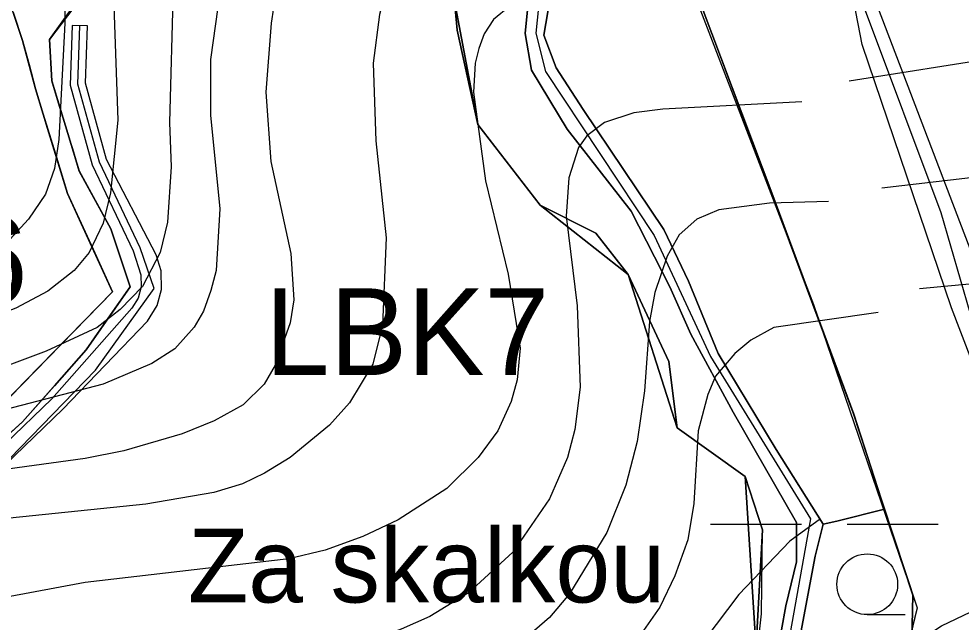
# Model space of a CAD drawing. Extents: x -1900516 to -575031, y -3809306 to -1157387.
# Drawn here: x -578987.9 to -578770.8, y -1159222.4 to -1159083.3 of the extents above; entities that cross this region are included whole.
import ezdxf

# ---------------------------------------------------------------- set-up
doc = ezdxf.new("R2010")
doc.units = 0
for name, color, linetype in [('01_MÍSTNÍ_NÁZVY', 7, 'Continuous'), ('01_OBVOD PÚ', 7, 'Continuous'), ('01_PARCELY_NÁVRH_PC', 7, 'Continuous'), ('01_PARCELY_NÁVRH_ŽP', 7, 'Continuous'), ('01_VRSTEVNICE', 7, 'Continuous'), ('02_KULTURY STAV', 7, 'Continuous'), ('03_PC_NÁVRH', 7, 'Continuous'), ('04_ZPF_OP_ORGAN', 7, 'Continuous'), ('05_VHO_V_TOK', 7, 'Continuous'), ('06_ÚSES_BK', 7, 'Continuous'), ('06_ÚSES_IP', 7, 'Continuous')]:
    doc.layers.add(name, color=color, linetype=linetype)

msp = doc.modelspace()

# ---------------------------------------------------------------- linework, layer by layer
at = {"layer": '01_OBVOD PÚ'}
msp.add_lwpolyline([(-578993.07, -1159173.58), (-578966.32, -1159146.21), (-578972.28, -1159133.19), (-578976.68, -1159123.58), (-578981.27, -1159108.56), (-578983.27, -1159102.02), (-578984.05, -1159099.45), (-578985.53, -1159093.95), (-578987.05, -1159088.32), (-578989.37, -1159081.4)], dxfattribs=at)
at = {"layer": '01_PARCELY_NÁVRH_PC'}
msp.add_lwpolyline([(-578999.92, -1159194.65), (-578977.74, -1159173.26), (-578958.23, -1159153.03), (-578956.02, -1159149.36), (-578955.02, -1159145.68), (-578955.13, -1159141.44), (-578956.29, -1159137.75), (-578967.7, -1159115.75), (-578972.58, -1159098.16), (-578972.11, -1159084.97), (-578975.61, -1159084.85), (-578976.1, -1159098.58), (-578971, -1159116.99), (-578961.55, -1159136.77), (-578959.79, -1159142.3), (-578959.73, -1159145.08), (-578960.42, -1159147.67), (-578961.87, -1159149.99), (-578980.3, -1159170.87), (-579002.02, -1159191.81)], dxfattribs=at)
at = {"layer": '01_PARCELY_NÁVRH_ŽP'}
for points in [[(-578972.07, -1159075.77), (-578980.86, -1159088.08), (-578980.33, -1159097.58), (-578977.16, -1159107.98), (-578976.36, -1159110.59), (-578975.56, -1159113.2), (-578973.97, -1159118.42), (-578970.34, -1159125.1), (-578966.74, -1159131.73), (-578962.23, -1159145.08), (-578967.3, -1159152.33), (-578972.38, -1159159.58), (-578979.72, -1159167.88), (-578987.06, -1159176.18), (-578995.06, -1159183.4)], [(-578993.07, -1159173.58), (-578979.7, -1159159.9), (-578966.32, -1159146.21), (-578969.3, -1159139.7), (-578972.28, -1159133.19), (-578976.68, -1159123.58), (-578982.27, -1159105.29), (-578984.05, -1159099.45), (-578987.05, -1159088.32), (-578989.24, -1159081.79)]]:
    msp.add_lwpolyline(points, dxfattribs=at)
at = {"layer": '01_VRSTEVNICE'}
for points in [[(-578909.33, -1159015.78), (-578918.97, -1159035.64), (-578926.52, -1159063.04), (-578929.74, -1159084.3), (-578931, -1159100.24), (-578929.88, -1159116.18), (-578925.26, -1159137.43), (-578924.57, -1159148.06), (-578925.4, -1159153.37), (-578928.84, -1159163.17), (-578931.36, -1159167.55), (-578936.22, -1159172.25), (-578942.88, -1159175.99), (-578950.29, -1159178.96), (-578963.71, -1159182.87), (-578972.66, -1159184.69), (-579002.31, -1159188.74), (-579014.89, -1159191.54), (-579073.61, -1159208.46), (-579108.57, -1159216.57), (-579135.42, -1159223.56), (-579145.66, -1159226.49), (-579157.79, -1159231.25), (-579178.62, -1159241.74)], [(-578934.07, -1159023.76), (-578933.79, -1159035.64), (-578934.63, -1159047.39), (-578938.13, -1159065), (-578942.04, -1159080.66), (-578943.72, -1159092.69), (-578943.72, -1159105.55), (-578941.62, -1159127.08), (-578942.46, -1159141.34), (-578943.66, -1159145.93), (-578945.4, -1159150.71), (-578947.5, -1159154.35), (-578951.97, -1159159.38), (-578957.28, -1159162.74), (-578968.47, -1159167.49), (-578993.08, -1159173.92)], [(-578950.01, -1159034.94), (-578952.39, -1159075.91), (-578953.23, -1159107.23), (-578952.81, -1159117.44), (-578953.65, -1159130.16), (-578955.33, -1159137.15), (-578959.38, -1159144.98), (-578964.54, -1159150.35), (-578969.87, -1159154.49), (-578981.61, -1159159.94), (-579047.05, -1159184.41), (-579064.67, -1159190.28), (-579086.2, -1159195.03), (-579137.09, -1159201.47), (-579142.98, -1159202.5), (-579150.8, -1159204.82), (-579163.66, -1159209.86), (-579181.14, -1159219.08), (-579204.21, -1159235.16), (-579204.77, -1159235.71)], [(-578965.67, -1159046.41), (-578966.23, -1159053.54), (-578966.23, -1159073.67), (-578965.11, -1159106.67), (-578966.79, -1159123.45), (-578968.47, -1159130.44), (-578971.69, -1159137.15), (-578975.18, -1159141.34), (-578981.19, -1159146.1), (-578988.6, -1159150.01), (-579008.18, -1159157.56), (-579059.91, -1159179.52), (-579073.61, -1159183.71), (-579087.32, -1159186.09), (-579132.62, -1159189.3), (-579142.69, -1159191.26), (-579148.19, -1159192.4), (-579156.11, -1159195.18), (-579177.78, -1159204.96), (-579197.22, -1159215.59), (-579203.16, -1159219.39)], [(-578873.53, -1159049.06), (-578881.78, -1159049.06), (-578884.99, -1159050.05), (-578888.49, -1159051.86), (-578894.78, -1159057.17), (-578900.38, -1159066.12), (-578904.85, -1159082.34), (-578906.25, -1159093.53), (-578905.69, -1159111.42), (-578903.31, -1159133.79), (-578904.15, -1159153.93), (-578906.39, -1159162.88), (-578911.7, -1159171.82), (-578916.32, -1159177), (-578925.4, -1159184.41), (-578931.28, -1159188.04), (-578936.41, -1159190.51), (-578943.02, -1159192.52), (-578958.68, -1159195.18), (-578990, -1159198.39)], [(-578976.02, -1159053.4), (-578977.28, -1159071.43), (-578977.28, -1159084.3), (-578978.68, -1159111.14), (-578979.65, -1159117.85), (-578981.75, -1159123.73), (-578985.67, -1159129.46), (-578990, -1159134.21), (-578996.85, -1159139.67), (-579027.75, -1159156.58), (-579055.72, -1159168.89), (-579065.64, -1159171.88), (-579079.21, -1159174.62), (-579090.95, -1159176.3), (-579132.06, -1159178.54), (-579145.76, -1159180.35), (-579153.59, -1159182.03), (-579167.15, -1159186.09), (-579177.92, -1159190.42), (-579189.67, -1159196.71), (-579196.78, -1159200.62), (-579201.55, -1159203.88)], [(-578874.79, -1159080.38), (-578878.56, -1159083.46), (-578880.73, -1159086.74), (-578881.92, -1159090.17), (-578882.76, -1159093.53), (-578883.18, -1159100.24), (-578880.38, -1159120.65), (-578875.21, -1159142.18), (-578872.41, -1159159.24), (-578873.11, -1159166.51), (-578874.51, -1159171.55), (-578877.58, -1159178.26), (-578882.06, -1159184.41), (-578889.33, -1159191.54), (-578900.52, -1159198.81), (-578908.65, -1159202.66), (-578917.3, -1159205.8), (-578925.68, -1159207.76), (-578972.66, -1159213.21), (-578991.12, -1159216.71)], [(-578761.67, -1159092.13), (-578796.63, -1159097.72)], [(-578807.54, -1159102.47), (-578839.55, -1159104.15), (-578846.27, -1159104.99), (-578852.98, -1159107.23), (-578857.03, -1159110.3), (-578858.99, -1159112.96), (-578861.23, -1159119.95), (-578861.82, -1159128.77), (-578859.27, -1159149.45), (-578858.57, -1159168.19), (-578859.83, -1159177.98), (-578861.51, -1159184.41), (-578865.7, -1159193.92), (-578874.09, -1159206.22), (-578884.3, -1159215.59), (-578893.24, -1159221.04), (-578899.82, -1159223.97), (-578911.42, -1159228.31), (-578924.01, -1159230.83), (-578933.79, -1159231.95), (-578953.93, -1159232.37), (-578968.47, -1159233.63), (-578985.25, -1159236.28), (-579000.91, -1159241.46)], [(-578768.67, -1159119.95), (-578789.08, -1159122.33)], [(-578801.38, -1159125.41), (-578814.95, -1159125.82), (-578826.69, -1159127.36), (-578831.72, -1159129.46), (-578835.78, -1159133.09), (-578838.58, -1159137.99), (-578841.37, -1159146.38), (-578842.63, -1159153.09), (-578843.75, -1159169.03), (-578845.43, -1159180.77), (-578848.08, -1159190.84), (-578852.42, -1159201.75), (-578861.09, -1159215.87), (-578865.7, -1159221.32), (-578874.23, -1159228.73), (-578885.7, -1159235.72), (-578893.53, -1159239.22), (-578902.66, -1159241.96), (-578915.06, -1159244.95), (-578963.71, -1159249.99), (-578978.82, -1159252.64), (-579009.02, -1159260.61)], [(-578638.35, -1159161.34), (-578649.4, -1159156.3), (-578666.18, -1159150.43), (-578682.95, -1159146.38), (-578708.12, -1159141.9), (-578718.54, -1159140.72), (-578729.66, -1159140.78), (-578780.41, -1159145.54)], [(-578789.92, -1159150.99), (-578813.97, -1159154.49), (-578819.28, -1159157.42), (-578823, -1159160.45), (-578827.39, -1159165.67), (-578829.21, -1159169.87), (-578831.44, -1159178.26), (-578832.42, -1159195.04), (-578833.82, -1159203.43), (-578836.76, -1159211.67), (-578840.25, -1159218.95), (-578846.69, -1159228.17), (-578859.83, -1159242.02), (-578869.34, -1159249.57), (-578880.38, -1159256.14), (-578888.21, -1159259.91), (-578900.8, -1159264.39), (-578913.38, -1159267.32), (-578931.99, -1159269.74), (-578950.76, -1159270.53), (-578967.77, -1159269.7), (-578983.57, -1159271.8), (-579008.46, -1159279.21)], [(-578803.2, -1159198.53), (-578810.33, -1159203.7), (-578822.08, -1159216.01), (-578842.91, -1159243.69), (-578854.52, -1159257.4), (-578861.02, -1159263.74), (-578870.18, -1159271.8), (-578883.46, -1159279.63), (-578890.17, -1159282.42), (-578901.35, -1159285.92), (-578912.54, -1159288.44), (-578937.15, -1159290.25), (-578959.52, -1159293.19), (-578986.37, -1159298.22), (-579017.69, -1159308.99)]]:
    msp.add_lwpolyline(points, dxfattribs=at)
at = {"layer": '02_KULTURY STAV'}
for points in [[(-578878.72, -1159008.57), (-578865.04, -1158997.83), (-578847.93, -1159038.28), (-578830.76, -1159080.15), (-578814.18, -1159124.01), (-578795.58, -1159174.4), (-578788.46, -1159196.37), (-578799.5, -1159199.1), (-578802.6, -1159199.77), (-578813.43, -1159182.6), (-578826.84, -1159160.45), (-578833.68, -1159143.82), (-578839.33, -1159131.86), (-578857.93, -1159104.24), (-578864.15, -1159094.62), (-578866.97, -1159087.11), (-578864.76, -1159074.04), (-578863.71, -1159058.92), (-578866.16, -1159041.64), (-578873.49, -1159017.14)], [(-578750.96, -1159216.07), (-578745.95, -1159212.49), (-578765.93, -1159143.8), (-578789.9, -1159081.01), (-578779.34, -1159073.2), (-578780.39, -1159072.12), (-578785.57, -1159075.82), (-578792.92, -1159081.42), (-578775.53, -1159127.99), (-578762.13, -1159174.04)], [(-578810.26, -1159237.93), (-578806.81, -1159219.87), (-578804.43, -1159207.13), (-578802.6, -1159199.77), (-578799.5, -1159199.1), (-578788.46, -1159196.37), (-578781.95, -1159216.17), (-578782.18, -1159226.7), (-578802.44, -1159228.63), (-578801.45, -1159255.16), (-578799.47, -1159271.13)]]:
    msp.add_lwpolyline(points, close=True, dxfattribs=at)
for points in [[(-578574.68, -1159052.93), (-578611.17, -1159089.26), (-578632.65, -1159109.54), (-578649.76, -1159125.08), (-578643.29, -1159133.51), (-578654.77, -1159144.71), (-578648.75, -1159152.41), (-578653.27, -1159153.89), (-578654.54, -1159154.47), (-578716.11, -1159192.14), (-578726.86, -1159198.82), (-578745.95, -1159212.49), (-578765.93, -1159143.8), (-578789.9, -1159081.01)], [(-578891.5, -1159058.08), (-578882.17, -1159107.67), (-578867.83, -1159126.24), (-578855, -1159132.74), (-578847.52, -1159142.23), (-578838.19, -1159162.33), (-578836.27, -1159177.56), (-578820.56, -1159188.8), (-578817.85, -1159232.29)], [(-578817.85, -1159232.29), (-578820.56, -1159188.8), (-578836.27, -1159177.56), (-578838.19, -1159162.33), (-578847.52, -1159142.23), (-578855, -1159132.74), (-578867.83, -1159126.24), (-578882.17, -1159107.67), (-578891.5, -1159058.08)], [(-578814.21, -1159235.22), (-578811.26, -1159218.58), (-578808.77, -1159208.5), (-578808.76, -1159199.41), (-578823.33, -1159173.97), (-578833.13, -1159156.03), (-578837.96, -1159145.12), (-578846.88, -1159127.63), (-578861.6, -1159108.78), (-578869.82, -1159095.18), (-578871.28, -1159086.72), (-578869.03, -1159064.22)], [(-578869.03, -1159064.22), (-578871.28, -1159086.72), (-578869.82, -1159095.18), (-578861.6, -1159108.78), (-578846.88, -1159127.63), (-578837.96, -1159145.12), (-578833.13, -1159156.03), (-578823.33, -1159173.97), (-578808.76, -1159199.41), (-578808.77, -1159208.5), (-578811.26, -1159218.58), (-578814.21, -1159235.22)], [(-578864.76, -1159074.04), (-578866.97, -1159087.11), (-578864.15, -1159094.62), (-578857.93, -1159104.24), (-578839.33, -1159131.86), (-578833.68, -1159143.82), (-578826.84, -1159160.45), (-578813.43, -1159182.6), (-578802.6, -1159199.77), (-578804.43, -1159207.13), (-578806.81, -1159219.87), (-578810.26, -1159237.93)], [(-578739.9, -1159419.59), (-578781.83, -1159408.23), (-578819.78, -1159397.99), (-578834.95, -1159391.81), (-578816.57, -1159357.48), (-578798.39, -1159319.53), (-578795.16, -1159304.69), (-578796.15, -1159292.03), (-578799.47, -1159271.13), (-578801.45, -1159255.16), (-578802.44, -1159228.63), (-578782.18, -1159226.7), (-578781.95, -1159216.17), (-578788.46, -1159196.37), (-578795.58, -1159174.4), (-578814.18, -1159124.01), (-578830.76, -1159080.15)], [(-578739.9, -1159419.59), (-578781.83, -1159408.23), (-578819.78, -1159397.99), (-578834.95, -1159391.81), (-578816.57, -1159357.48), (-578798.39, -1159319.53), (-578795.16, -1159304.69), (-578796.15, -1159292.03), (-578799.47, -1159271.13), (-578801.45, -1159255.16), (-578802.44, -1159228.63), (-578782.18, -1159226.7), (-578781.95, -1159216.17), (-578788.46, -1159196.37), (-578795.58, -1159174.4), (-578814.18, -1159124.01), (-578830.76, -1159080.15)], [(-578993.07, -1159173.58), (-578966.32, -1159146.21), (-578972.28, -1159133.19), (-578976.68, -1159123.58), (-578981.27, -1159108.56), (-578983.27, -1159102.02), (-578984.05, -1159099.45), (-578985.53, -1159093.95), (-578987.05, -1159088.32), (-578989.24, -1159081.79)], [(-578792.92, -1159081.42), (-578775.53, -1159127.99), (-578762.13, -1159174.04)], [(-578792.92, -1159081.42), (-578775.53, -1159127.99), (-578762.13, -1159174.04)], [(-578828.6, -1159199.77), (-578807.6, -1159199.77)], [(-578797.1, -1159199.77), (-578776.1, -1159199.77)], [(-578792.47, -1159220.64), (-578783.72, -1159220.64)]]:
    msp.add_lwpolyline(points, dxfattribs=at)
msp.add_circle((-578792.47, -1159213.64), 7, dxfattribs=at)
at = {"layer": '03_PC_NÁVRH'}
msp.add_lwpolyline([(-579215.95, -1159443), (-579197.17, -1159431.39), (-579158.1, -1159403.48), (-579144.16, -1159382.97), (-579128.89, -1159358.02), (-579121.35, -1159334.32), (-579125.5, -1159322.44), (-579117.12, -1159313.8), (-579116.13, -1159309.29), (-579151.57, -1159271.29), (-579158.84, -1159254.47), (-579157.24, -1159244.6), (-579150.76, -1159236.03), (-579103.57, -1159230.86), (-579083.6, -1159225.15), (-579037.45, -1159215.89), (-578997.46, -1159192.24), (-578970.28, -1159164.33), (-578956.73, -1159145.48), (-578959.93, -1159136.11), (-578969.35, -1159116.37), (-578974.34, -1159098.37), (-578973.86, -1159084.91)], dxfattribs=at)
at = {"layer": '04_ZPF_OP_ORGAN'}
for points in [[(-578762.04, -1159183.36), (-578765.87, -1159168.76), (-578773.07, -1159149.94), (-578793.65, -1159089.25), (-578795.58, -1159079.34), (-578795.27, -1159075.99), (-578791.37, -1159071.9), (-578791.69, -1159068.99), (-578805.61, -1158990.49), (-578808.68, -1158974.26), (-578809.14, -1158971.01), (-578808.11, -1158968.03), (-578813.28, -1158970.34), (-578834.9, -1158979.44), (-578865.04, -1158997.83), (-578830.76, -1159080.15), (-578795.77, -1159174.05), (-578789.1, -1159194.41), (-578781, -1159219.07), (-578782.87, -1159226.66), (-578779.45, -1159225.94), (-578775.36, -1159223.24), (-578765.19, -1159218.39), (-578755.01, -1159213.54)], [(-579003.06, -1159190.63), (-578987.06, -1159176.18), (-578972.38, -1159159.58), (-578962.23, -1159145.08), (-578966.74, -1159131.73), (-578974, -1159118.37), (-578980.33, -1159097.58), (-578980.86, -1159088.08), (-578964.24, -1159066.22)], [(-578964.24, -1159066.22), (-578980.86, -1159088.08), (-578980.33, -1159097.58), (-578974, -1159118.37), (-578966.74, -1159131.73), (-578962.23, -1159145.08), (-578972.38, -1159159.58), (-578987.06, -1159176.18), (-579003.06, -1159190.63)], [(-578888.29, -1159070.91), (-578886.95, -1159085.92), (-578882.17, -1159107.67), (-578867.83, -1159126.24), (-578847.52, -1159142.23), (-578836.27, -1159177.56), (-578820.56, -1159188.8), (-578816.56, -1159201.13), (-578818.55, -1159236.29), (-578810.26, -1159256.1), (-578807.96, -1159269.74), (-578810.29, -1159280.86), (-578813.72, -1159289.8), (-578823.43, -1159305.7), (-578832.58, -1159325.31), (-578839.96, -1159348.66), (-578853.83, -1159370.03), (-578860.48, -1159378.42), (-578882.11, -1159367.01), (-578892.7, -1159362.98), (-578915.87, -1159356.24), (-578931.16, -1159353.47), (-578947.72, -1159352.64), (-579017.93, -1159351.06)], [(-579017.93, -1159351.06), (-578947.72, -1159352.64), (-578931.16, -1159353.47), (-578915.87, -1159356.24), (-578892.7, -1159362.98), (-578882.11, -1159367.01), (-578860.48, -1159378.42), (-578853.83, -1159370.03), (-578839.96, -1159348.66), (-578832.58, -1159325.31), (-578823.43, -1159305.7), (-578813.72, -1159289.8), (-578810.29, -1159280.86), (-578807.96, -1159269.74), (-578810.26, -1159256.1), (-578818.55, -1159236.29), (-578816.56, -1159201.13), (-578820.56, -1159188.8), (-578836.27, -1159177.56), (-578847.52, -1159142.23), (-578867.83, -1159126.24), (-578882.17, -1159107.67), (-578886.95, -1159085.92), (-578888.29, -1159070.91)], [(-578830.76, -1159080.15), (-578795.77, -1159174.05), (-578789.1, -1159194.41), (-578781, -1159219.07), (-578782.87, -1159226.66), (-578779.45, -1159225.94), (-578775.36, -1159223.24), (-578765.19, -1159218.39), (-578755.01, -1159213.54), (-578758.9, -1159200.51), (-578762.04, -1159183.36), (-578765.87, -1159168.76), (-578773.07, -1159149.94), (-578793.65, -1159089.25), (-578795.58, -1159079.34)]]:
    msp.add_lwpolyline(points, dxfattribs=at)
at = {"layer": '05_VHO_V_TOK'}
for p, q in [((-578866.11, -1159059.66), (-578868.8, -1159086.64)), ((-578868.8, -1159086.64), (-578866.6, -1159095.47)), ((-578866.6, -1159095.47), (-578841.54, -1159133.24)), ((-578841.54, -1159133.24), (-578828.61, -1159161.13)), ((-578828.61, -1159161.13), (-578805.55, -1159198.6)), ((-578805.55, -1159198.6), (-578812.13, -1159235.63))]:
    msp.add_line(p, q, dxfattribs=at)
at = {"layer": '06_ÚSES_BK'}
for p, q in [((-578839.34, -1159059.22), (-578804.88, -1159149.2)), ((-578886.95, -1159085.92), (-578888.29, -1159070.91)), ((-578882.17, -1159107.67), (-578886.95, -1159085.92)), ((-578867.83, -1159126.24), (-578882.17, -1159107.67)), ((-578855, -1159132.74), (-578867.83, -1159126.24)), ((-578847.52, -1159142.23), (-578855, -1159132.74)), ((-578838.19, -1159162.33), (-578847.52, -1159142.23)), ((-578804.88, -1159149.2), (-578781, -1159219.07)), ((-578836.27, -1159177.56), (-578838.19, -1159162.33)), ((-578820.56, -1159188.8), (-578836.27, -1159177.56)), ((-578816.56, -1159201.13), (-578820.56, -1159188.8)), ((-578816.85, -1159220.47), (-578816.56, -1159201.13)), ((-578781, -1159219.07), (-578783.28, -1159228.64)), ((-578817.7, -1159228.38), (-578816.85, -1159220.47))]:
    msp.add_line(p, q, dxfattribs=at)
at = {"layer": '06_ÚSES_IP'}
for points in [[(-578995.06, -1159183.4), (-578987.06, -1159176.18), (-578979.72, -1159167.88), (-578972.38, -1159159.58), (-578967.3, -1159152.33), (-578962.23, -1159145.08), (-578964.48, -1159138.4), (-578966.74, -1159131.73), (-578973.97, -1159118.42), (-578975.56, -1159113.2), (-578978.74, -1159102.78), (-578980.33, -1159097.58), (-578980.86, -1159088.08), (-578972.07, -1159075.77)], [(-578989.24, -1159081.79), (-578987.05, -1159088.32), (-578985.55, -1159093.88), (-578984.05, -1159099.45), (-578982.27, -1159105.29), (-578979.48, -1159114.44), (-578976.68, -1159123.58), (-578974.48, -1159128.38), (-578970.79, -1159136.44), (-578966.32, -1159146.21), (-578973.01, -1159153.06), (-578979.7, -1159159.9), (-578986.38, -1159166.74), (-578993.07, -1159173.58)]]:
    msp.add_lwpolyline(points, dxfattribs=at)

# ---------------------------------------------------------------- texts
at = {"layer": '01_MÍSTNÍ_NÁZVY'}
msp.add_text('Za skalkou', height=17, dxfattribs=at).set_placement((-578948.94, -1159217.84))
at = {"layer": '06_ÚSES_BK'}
msp.add_text('LBK7', height=20, dxfattribs=at).set_placement((-578931.18, -1159165.43))
at = {"layer": '06_ÚSES_IP'}
msp.add_text('IP26', height=20, dxfattribs=at).set_placement((-579040.92, -1159148.96))

doc.saveas('drawing.dxf')
